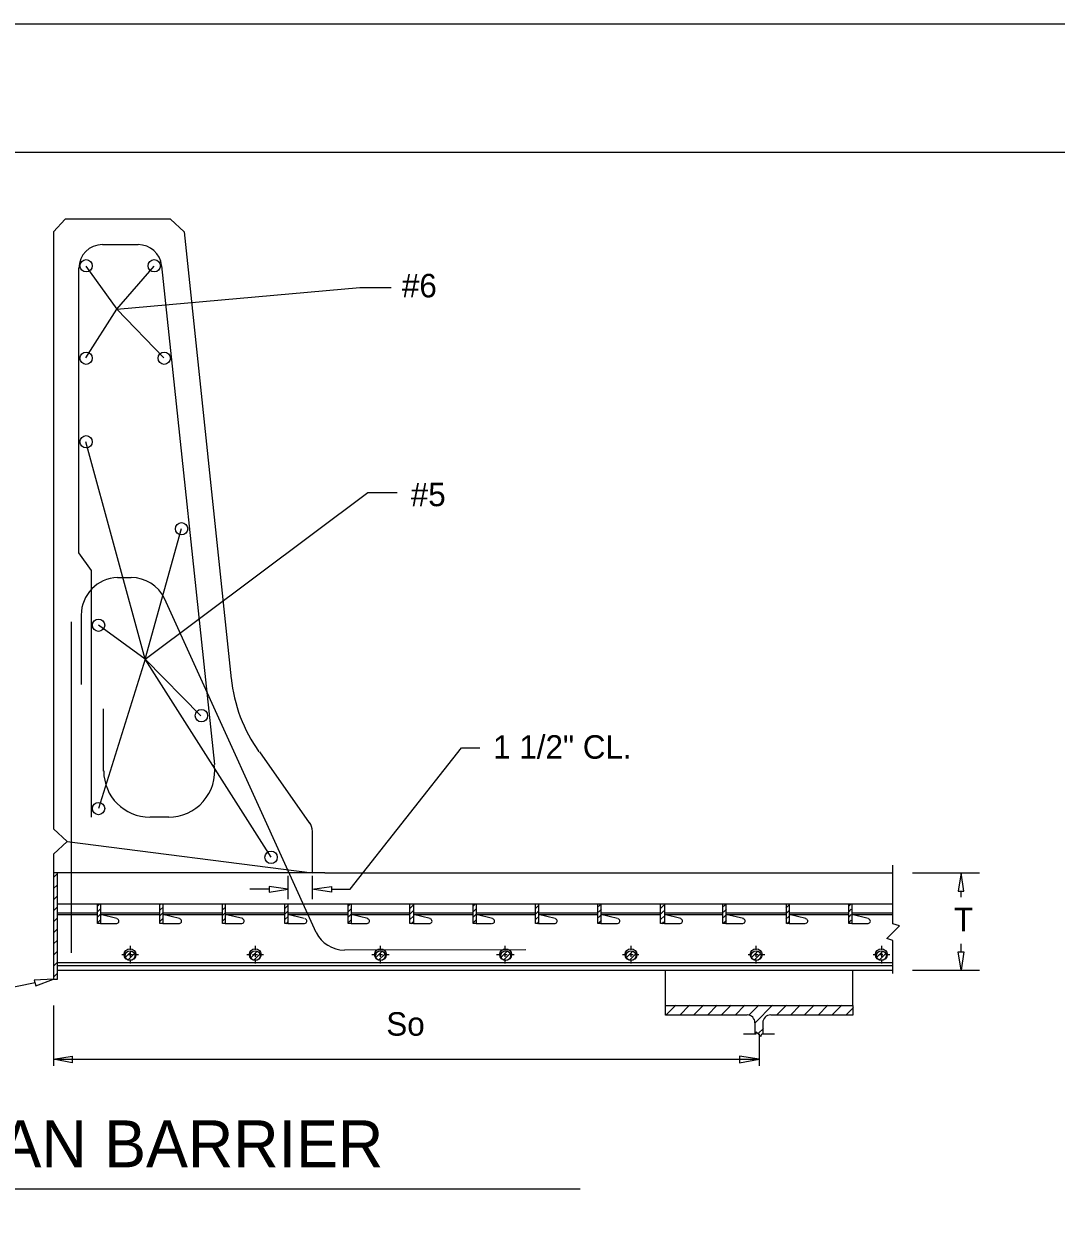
# Model space of a CAD drawing. Extents: x -24512 to -22484, y 4569 to 6351.
# Drawn here: x -23745.6 to -23613.7, y 6199 to 6351 of the extents above; entities that cross this region are included whole.
import ezdxf

# ---------------------------------------------------------------- set-up
doc = ezdxf.new("R2010")
doc.units = 0
for name, color, linetype in [('10', 7, 'Continuous'), ('11', 7, 'Continuous'), ('2', 7, 'Continuous'), ('4', 7, 'Continuous'), ('5', 7, 'Continuous'), ('8', 7, 'Continuous'), ('PLT-BNDY', 7, 'Continuous')]:
    doc.layers.add(name, color=color, linetype=linetype)

# ---------------------------------------------------------------- blocks, each defined once
blk = doc.blocks.new('JUQ000')
at = {"layer": '4'}
for p, q in [((71.0975, 21.771125), (71.421875, 22.095625)), ((71.237875, 21.6265), (71.566625, 21.95525))]:
    blk.add_line(p, q, dxfattribs=at)
blk = doc.blocks.new('JUQ001')
at = {"layer": '4'}
for p, q in [((66.419125, 24.506), (66.4355, 24.522375)), ((66.419125, 24.220875), (66.570375, 24.372125)), ((66.419125, 23.93575), (66.570375, 24.087)), ((66.419125, 23.650625), (66.570375, 23.801875)), ((66.567875, 23.514375), (66.570375, 23.51675))]:
    blk.add_line(p, q, dxfattribs=at)
blk = doc.blocks.new('_X')
at = {"layer": '4'}
for p, q in [((63.193375, 24.416625), (63.299125, 24.522375)), ((63.193375, 24.1315), (63.3445, 24.282625)), ((63.193375, 23.846375), (63.3445, 23.9975)), ((63.193375, 23.56125), (63.3445, 23.712375))]:
    blk.add_line(p, q, dxfattribs=at)
blk = doc.blocks.new('JUQ004')
at = {"layer": '4'}
for p, q in [((69.644875, 24.310375), (69.796125, 24.4615)), ((69.644875, 24.02525), (69.796125, 24.176375)), ((69.644875, 23.740125), (69.796125, 23.89125)), ((69.70425, 23.514375), (69.796125, 23.60625))]:
    blk.add_line(p, q, dxfattribs=at)
blk = doc.blocks.new('JUQ002')
at = {"layer": '4'}
for p, q in [((72.87075, 24.39975), (72.993375, 24.522375)), ((72.87075, 24.114625), (73.021875, 24.265875)), ((72.87075, 23.8295), (73.021875, 23.98075)), ((72.87075, 23.544375), (73.021875, 23.695625))]:
    blk.add_line(p, q, dxfattribs=at)
blk = doc.blocks.new('JUQ003')
at = {"layer": '4'}
for p, q in [((89.35625, 63.69525), (89.860375, 64.19925)), ((90.069125, 63.69525), (90.573125, 64.19925)), ((90.781875, 63.69525), (91.285875, 64.19925)), ((91.49475, 63.69525), (91.99875, 64.19925)), ((92.2075, 63.69525), (92.7115, 64.19925)), ((92.920375, 63.69525), (93.424375, 64.19925)), ((93.628875, 63.691), (94.137125, 64.19925)), ((93.972625, 63.321875), (94.85, 64.19925)), ((95.05875, 63.69525), (95.56275, 64.19925)), ((95.7715, 63.69525), (96.275625, 64.19925)), ((96.484375, 63.69525), (96.988375, 64.19925)), ((97.197125, 63.69525), (97.70125, 64.19925)), ((97.91, 63.69525), (98.414, 64.19925)), ((98.62275, 63.69525), (99.014, 64.0865)), ((94.121125, 62.757625), (94.377, 63.013375))]:
    blk.add_line(p, q, dxfattribs=at)

msp = doc.modelspace()

# ---------------------------------------------------------------- linework, layer by layer
at = {"layer": '10'}
for p, q in [((-23737.67, 6320.06), (-23733.68, 6314.58)), ((-23733.68, 6314.58), (-23728.94, 6320.06)), ((-23737.67, 6308.34), (-23733.68, 6314.58)), ((-23733.68, 6314.58), (-23727.69, 6308.34)), ((-23730.06, 6269.81), (-23737.67, 6297.62)), ((-23730.06, 6269.81), (-23701.63, 6291.14)), ((-23701.63, 6291.14), (-23697.89, 6291.14)), ((-23730.06, 6269.81), (-23725.45, 6286.52)), ((-23733.6, 6280.26), (-23731.87, 6280.26)), ((-23730.06, 6269.81), (-23736.05, 6274.18)), ((-23730.06, 6269.81), (-23736.05, 6250.74)), ((-23713.98, 6244.5), (-23730.06, 6269.81)), ((-23722.95, 6262.58), (-23730.06, 6269.81)), ((-23703.88, 6240.39), (-23689.66, 6258.46)), ((-23689.66, 6258.46), (-23687.29, 6258.46)), ((-23711.86, 6242.13), (-23711.86, 6239.14)), ((-23708.74, 6242.13), (-23708.74, 6239.14)), ((-23632.03, 6242.51), (-23623.44, 6242.51)), ((-23714.23, 6240.39), (-23716.72, 6240.39)), ((-23706.25, 6240.39), (-23703.88, 6240.39)), ((-23625.81, 6239.39), (-23625.81, 6240.14)), ((-23731.93, 6232.66), (-23731.93, 6233.16)), ((-23715.97, 6232.66), (-23715.97, 6233.16)), ((-23700.01, 6232.66), (-23700.01, 6233.16)), ((-23684.05, 6232.66), (-23684.05, 6233.16)), ((-23667.97, 6232.66), (-23667.97, 6233.16)), ((-23652.01, 6232.66), (-23652.01, 6233.16)), ((-23635.92, 6232.66), (-23635.92, 6233.16)), ((-23625.81, 6232.41), (-23625.81, 6233.41)), ((-23732.55, 6232.03), (-23733.05, 6232.03)), ((-23731.68, 6232.03), (-23732.3, 6232.03)), ((-23731.93, 6231.78), (-23731.93, 6232.28)), ((-23730.93, 6232.03), (-23731.43, 6232.03)), ((-23716.59, 6232.03), (-23717.09, 6232.03)), ((-23715.72, 6232.03), (-23716.34, 6232.03)), ((-23715.97, 6231.78), (-23715.97, 6232.28)), ((-23714.97, 6232.03), (-23715.47, 6232.03)), ((-23700.51, 6232.03), (-23701.13, 6232.03)), ((-23699.76, 6232.03), (-23700.26, 6232.03)), ((-23700.01, 6231.78), (-23700.01, 6232.28)), ((-23698.89, 6232.03), (-23699.39, 6232.03)), ((-23684.55, 6232.03), (-23685.17, 6232.03)), ((-23683.8, 6232.03), (-23684.3, 6232.03)), ((-23684.05, 6231.78), (-23684.05, 6232.28)), ((-23682.93, 6232.03), (-23683.43, 6232.03)), ((-23668.59, 6232.03), (-23669.09, 6232.03)), ((-23667.72, 6232.03), (-23668.22, 6232.03)), ((-23667.97, 6231.78), (-23667.97, 6232.28)), ((-23666.97, 6232.03), (-23667.34, 6232.03)), ((-23652.63, 6232.03), (-23653, 6232.03)), ((-23651.76, 6232.03), (-23652.26, 6232.03)), ((-23652.01, 6231.78), (-23652.01, 6232.28)), ((-23650.88, 6232.03), (-23651.38, 6232.03)), ((-23636.54, 6232.03), (-23637.04, 6232.03)), ((-23635.8, 6232.03), (-23636.3, 6232.03)), ((-23635.92, 6231.78), (-23635.92, 6232.28)), ((-23634.92, 6232.03), (-23635.42, 6232.03)), ((-23731.93, 6230.91), (-23731.93, 6231.41)), ((-23715.97, 6230.91), (-23715.97, 6231.41)), ((-23700.01, 6230.91), (-23700.01, 6231.41)), ((-23684.05, 6230.91), (-23684.05, 6231.41)), ((-23667.97, 6230.91), (-23667.97, 6231.41)), ((-23652.01, 6230.91), (-23652.01, 6231.41)), ((-23635.92, 6230.91), (-23635.92, 6231.41)), ((-23632.03, 6230.04), (-23623.44, 6230.04)), ((-23744.15, 6228.42), (-23757.24, 6225.8)), ((-23741.78, 6225.55), (-23741.78, 6217.82)), ((-23651.63, 6221.93), (-23651.63, 6217.82)), ((-23741.78, 6218.69), (-23651.63, 6218.69))]:
    msp.add_line(p, q, dxfattribs=at)
msp.add_lwpolyline([(-23733.68, 6314.58), (-23702.63, 6317.32), (-23698.64, 6317.32)], dxfattribs=at)
for points in [[(-23626.19, 6240.14), (-23625.44, 6240.14), (-23625.81, 6242.51)], [(-23714.23, 6240.76), (-23714.23, 6240.01), (-23711.86, 6240.39)], [(-23706.25, 6240.76), (-23706.25, 6240.01), (-23708.74, 6240.39)], [(-23626.19, 6232.41), (-23625.44, 6232.41), (-23625.81, 6230.04)], [(-23744.27, 6228.79), (-23744.03, 6228.04), (-23741.78, 6228.92)], [(-23739.41, 6219.07), (-23739.41, 6218.19), (-23741.78, 6218.69)], [(-23654.13, 6219.07), (-23654.13, 6218.19), (-23651.63, 6218.69)]]:
    msp.add_lwpolyline(points, close=True, dxfattribs=at)
for centre, radius, start, end in [((-23735.54, 6319.81), 3, 90, 180), ((-23730.96, 6319.81), 3, 6.0542, 90), ((-23733.45, 6275.46), 4.8, 91.8539, 180), ((-23731.91, 6275.46), 4.8, 26.0753, 89.5289), ((-23704.62, 6236.63), 4, 206.1039, 270.062)]:
    msp.add_arc(centre, radius, start, end, dxfattribs=at)
at = {"layer": '11'}
msp.add_line((-23674.47, 6202.06), (-23795.04, 6202.06), dxfattribs=at)
at = {"layer": '2'}
msp.add_line((-24137.79, 6334.63), (-23353.75, 6334.63), dxfattribs=at)
at = {"layer": '4'}
for p, q in [((-23741.78, 6241.89), (-23741.32, 6242.35)), ((-23741.78, 6240.48), (-23741.32, 6240.94)), ((-23741.78, 6239.06), (-23741.32, 6239.52)), ((-23741.78, 6237.65), (-23741.32, 6238.11)), ((-23741.78, 6236.24), (-23741.32, 6236.69)), ((-23741.78, 6234.82), (-23741.32, 6235.28)), ((-23741.78, 6233.41), (-23741.32, 6233.86)), ((-23741.78, 6231.99), (-23741.32, 6232.45)), ((-23741.78, 6230.58), (-23741.32, 6231.04)), ((-23741.78, 6229.16), (-23741.32, 6229.62))]:
    msp.add_line(p, q, dxfattribs=at)
at = {"layer": '5'}
for p, q in [((-23707.12, 6242.51), (-23634.54, 6242.51)), ((-23741.28, 6238.52), (-23736.17, 6238.52)), ((-23735.8, 6238.52), (-23728.19, 6238.52)), ((-23727.82, 6238.52), (-23720.21, 6238.52)), ((-23719.84, 6238.52), (-23712.23, 6238.52)), ((-23711.86, 6238.52), (-23704.13, 6238.52)), ((-23703.75, 6238.52), (-23696.27, 6238.52)), ((-23695.77, 6238.52), (-23688.17, 6238.52)), ((-23687.79, 6238.52), (-23680.19, 6238.52)), ((-23679.81, 6238.52), (-23672.21, 6238.52)), ((-23671.83, 6238.52), (-23664.23, 6238.52)), ((-23663.73, 6238.52), (-23656.25, 6238.52)), ((-23655.87, 6238.52), (-23648.14, 6238.52)), ((-23647.77, 6238.52), (-23640.16, 6238.52)), ((-23639.79, 6238.52), (-23634.54, 6238.52)), ((-23741.28, 6237.4), (-23736.17, 6237.4)), ((-23741.28, 6237.15), (-23736.17, 6237.15)), ((-23735.8, 6237.4), (-23728.19, 6237.4)), ((-23735.8, 6237.15), (-23728.19, 6237.15)), ((-23733.68, 6236.65), (-23735.8, 6237.15)), ((-23735.8, 6236.02), (-23733.68, 6236.02)), ((-23727.82, 6237.4), (-23720.21, 6237.4)), ((-23727.82, 6237.15), (-23720.21, 6237.15)), ((-23725.7, 6236.65), (-23727.82, 6237.15)), ((-23727.82, 6236.02), (-23725.7, 6236.02)), ((-23719.84, 6237.4), (-23712.23, 6237.4)), ((-23719.84, 6237.15), (-23712.23, 6237.15)), ((-23717.59, 6236.65), (-23719.84, 6237.15)), ((-23719.84, 6236.02), (-23717.72, 6236.02)), ((-23711.86, 6237.4), (-23704.13, 6237.4)), ((-23711.86, 6237.15), (-23704.13, 6237.15)), ((-23709.74, 6236.65), (-23711.86, 6237.15)), ((-23711.86, 6236.02), (-23709.74, 6236.02)), ((-23703.75, 6237.4), (-23696.27, 6237.4)), ((-23703.75, 6237.15), (-23696.27, 6237.15)), ((-23701.63, 6236.65), (-23703.75, 6237.15)), ((-23703.75, 6236.02), (-23701.76, 6236.02)), ((-23695.77, 6237.4), (-23688.17, 6237.4)), ((-23695.77, 6237.15), (-23688.17, 6237.15)), ((-23693.65, 6236.65), (-23695.77, 6237.15)), ((-23695.77, 6236.02), (-23693.65, 6236.02)), ((-23687.79, 6237.4), (-23680.19, 6237.4)), ((-23687.79, 6237.15), (-23680.19, 6237.15)), ((-23685.67, 6236.65), (-23687.79, 6237.15)), ((-23687.79, 6236.02), (-23685.8, 6236.02)), ((-23679.81, 6237.4), (-23672.21, 6237.4)), ((-23679.81, 6237.15), (-23672.21, 6237.15)), ((-23677.69, 6236.65), (-23679.81, 6237.15)), ((-23679.81, 6236.02), (-23677.69, 6236.02)), ((-23671.83, 6237.4), (-23664.23, 6237.4)), ((-23671.83, 6237.15), (-23664.23, 6237.15)), ((-23669.71, 6236.65), (-23671.83, 6237.15)), ((-23671.83, 6236.02), (-23669.71, 6236.02)), ((-23663.73, 6237.4), (-23656.25, 6237.4)), ((-23663.73, 6237.15), (-23656.25, 6237.15)), ((-23661.61, 6236.65), (-23663.73, 6237.15)), ((-23663.73, 6236.02), (-23661.73, 6236.02)), ((-23655.87, 6237.4), (-23648.14, 6237.4)), ((-23655.87, 6237.15), (-23648.14, 6237.15)), ((-23653.63, 6236.65), (-23655.87, 6237.15)), ((-23655.87, 6236.02), (-23653.75, 6236.02)), ((-23647.77, 6237.4), (-23640.16, 6237.4)), ((-23647.77, 6237.15), (-23640.16, 6237.15)), ((-23645.65, 6236.65), (-23647.77, 6237.15)), ((-23647.77, 6236.02), (-23645.77, 6236.02)), ((-23639.79, 6237.4), (-23634.54, 6237.4)), ((-23637.67, 6236.65), (-23639.79, 6237.15)), ((-23639.79, 6237.15), (-23634.54, 6237.15)), ((-23639.79, 6236.02), (-23637.67, 6236.02)), ((-23741.28, 6231.04), (-23634.54, 6231.04)), ((-23741.28, 6230.66), (-23634.54, 6230.66)), ((-23741.28, 6230.04), (-23634.54, 6230.04)), ((-23663.6, 6225.55), (-23663.6, 6230.04)), ((-23639.66, 6225.55), (-23639.66, 6230.04)), ((-23663.6, 6224.3), (-23663.6, 6225.55)), ((-23663.6, 6225.55), (-23639.66, 6225.55)), ((-23639.66, 6225.55), (-23639.66, 6224.3)), ((-23653.13, 6224.3), (-23663.6, 6224.3)), ((-23639.66, 6224.3), (-23650.14, 6224.3)), ((-23652.13, 6221.93), (-23652.13, 6223.31)), ((-23651.13, 6223.31), (-23651.13, 6221.93)), ((-23653.63, 6221.93), (-23652.13, 6221.93)), ((-23651.13, 6221.93), (-23649.64, 6221.93))]:
    msp.add_line(p, q, dxfattribs=at)
for points in [[(-23741.78, 6228.92), (-23741.28, 6228.92), (-23741.28, 6242.51), (-23741.78, 6242.51)], [(-23735.8, 6238.52), (-23735.8, 6236.02), (-23736.17, 6236.02), (-23736.17, 6238.52)], [(-23727.82, 6238.52), (-23727.82, 6236.02), (-23728.19, 6236.02), (-23728.19, 6238.52)], [(-23719.84, 6238.52), (-23719.84, 6236.02), (-23720.21, 6236.02), (-23720.21, 6238.52)], [(-23711.86, 6238.52), (-23711.86, 6236.02), (-23712.23, 6236.02), (-23712.23, 6238.52)], [(-23703.75, 6238.52), (-23703.75, 6236.02), (-23704.13, 6236.02), (-23704.13, 6238.52)], [(-23695.77, 6238.52), (-23695.77, 6236.02), (-23696.27, 6236.02), (-23696.27, 6238.52)], [(-23687.79, 6238.52), (-23687.79, 6236.02), (-23688.17, 6236.02), (-23688.17, 6238.52)], [(-23679.81, 6238.52), (-23679.81, 6236.02), (-23680.19, 6236.02), (-23680.19, 6238.52)], [(-23671.83, 6238.52), (-23671.83, 6236.02), (-23672.21, 6236.02), (-23672.21, 6238.52)], [(-23663.73, 6238.52), (-23663.73, 6236.02), (-23664.23, 6236.02), (-23664.23, 6238.52)], [(-23655.87, 6238.52), (-23655.87, 6236.02), (-23656.25, 6236.02), (-23656.25, 6238.52)], [(-23647.77, 6238.52), (-23647.77, 6236.02), (-23648.14, 6236.02), (-23648.14, 6238.52)], [(-23639.79, 6238.52), (-23639.79, 6236.02), (-23640.16, 6236.02), (-23640.16, 6238.52)]]:
    msp.add_lwpolyline(points, close=True, dxfattribs=at)
for points in [[(-23634.54, 6229.62), (-23634.54, 6233.86), (-23635.29, 6234.11), (-23633.66, 6235.73), (-23634.54, 6235.98), (-23634.54, 6243.46)], [(-23652.13, 6221.93), (-23652.01, 6221.93), (-23652.01, 6222.18), (-23651.38, 6221.56), (-23651.26, 6221.93), (-23651.13, 6221.93)]]:
    msp.add_lwpolyline(points, dxfattribs=at)
for centre, radius in [((-23732.01, 6232.05), 0.75), ((-23732.01, 6231.92), 0.625), ((-23716.01, 6232.05), 0.75), ((-23716.01, 6231.92), 0.625), ((-23700.01, 6232.05), 0.75), ((-23700.01, 6231.92), 0.625), ((-23684.01, 6232.05), 0.75), ((-23684.01, 6231.92), 0.625), ((-23668, 6232.05), 0.75), ((-23668, 6231.92), 0.625), ((-23652, 6232.05), 0.75), ((-23652, 6231.92), 0.625), ((-23636, 6232.05), 0.75), ((-23636, 6231.92), 0.625)]:
    msp.add_circle(centre, radius, dxfattribs=at)
for centre, radius, start, end in [((-23733.73, 6236.33), 0.305, 271.249, 76.5605), ((-23725.72, 6236.33), 0.305, 271.249, 76.5605), ((-23717.72, 6236.33), 0.305, 271.249, 76.5605), ((-23709.72, 6236.33), 0.305, 271.249, 76.5605), ((-23701.72, 6236.33), 0.305, 271.249, 76.5605), ((-23693.72, 6236.33), 0.305, 271.249, 76.5605), ((-23685.72, 6236.33), 0.305, 271.249, 76.5605), ((-23677.72, 6236.33), 0.305, 271.249, 76.5605), ((-23669.72, 6236.33), 0.305, 271.249, 76.5605), ((-23661.71, 6236.33), 0.305, 271.249, 76.5605), ((-23653.71, 6236.33), 0.305, 271.249, 76.5605), ((-23645.71, 6236.33), 0.305, 271.249, 76.5605), ((-23637.71, 6236.33), 0.305, 271.249, 76.5605), ((-23653.15, 6223.33), 1, 0, 90), ((-23650.15, 6223.33), 1, 90, 180)]:
    msp.add_arc(centre, radius, start, end, dxfattribs=at)
at = {"layer": '8'}
for p, q in [((-23735.54, 6322.81), (-23730.96, 6322.81)), ((-23738.54, 6283.41), (-23738.54, 6319.81)), ((-23727.97, 6320.12), (-23721.21, 6256.35)), ((-23736.92, 6249.61), (-23736.92, 6280.29)), ((-23708.21, 6234.87), (-23727.6, 6277.57)), ((-23739.49, 6232.27), (-23739.49, 6274.58)), ((-23738.25, 6275.46), (-23738.25, 6266.57)), ((-23735.42, 6255.48), (-23735.42, 6263.46)), ((-23727.07, 6249.61), (-23729.44, 6249.61)), ((-23681.43, 6232.66), (-23704.62, 6232.63))]:
    msp.add_line(p, q, dxfattribs=at)
msp.add_lwpolyline([(-23736.92, 6280.29), (-23736.92, 6281.16), (-23738.54, 6283.41)], dxfattribs=at)
for centre in [(-23737.62, 6320.1), (-23728.91, 6320.1), (-23737.62, 6308.29), (-23727.64, 6308.29), (-23737.62, 6297.6), (-23725.42, 6286.48), (-23736.03, 6274.15), (-23722.89, 6262.59), (-23736.03, 6250.71), (-23713.99, 6244.48)]:
    msp.add_circle(centre, 0.788, dxfattribs=at)
for centre, start, end in [((-23727.1, 6255.52), 270, 7.4397), ((-23729.46, 6255.52), 180, 270)]:
    msp.add_arc(centre, 5.91, start, end, dxfattribs=at)
at = {"layer": 'PLT-BNDY'}
for p, q in [((-23741.78, 6324.43), (-23740.28, 6326.05)), ((-23726.82, 6326.05), (-23740.28, 6326.05)), ((-23725.07, 6324.43), (-23726.82, 6326.05)), ((-23741.78, 6324.43), (-23741.78, 6248.12)), ((-23725.07, 6324.43), (-23719.09, 6267.32)), ((-23715.47, 6257.97), (-23709.11, 6248.87)), ((-23741.78, 6248.12), (-23740.04, 6246.5)), ((-23708.74, 6247.87), (-23708.74, 6242.51)), ((-23741.78, 6244.88), (-23740.04, 6246.5)), ((-23740.04, 6246.5), (-23708.74, 6242.51)), ((-23741.78, 6244.88), (-23741.78, 6242.51)), ((-23707.12, 6242.51), (-23741.78, 6242.51))]:
    msp.add_line(p, q, dxfattribs=at)
msp.add_lwpolyline([(-23338.75, 5757.04), (-24179.75, 5757.04), (-24179.75, 6351.04), (-23338.75, 6351.04)], close=True, dxfattribs=at)
for centre, radius, start, end in [((-23699.51, 6269.43), 19.69, 185.9906, 215.5377), ((-23710.68, 6247.8), 1.97, 0, 35.5377)]:
    msp.add_arc(centre, radius, start, end, dxfattribs=at)

# ---------------------------------------------------------------- block references
at = {"layer": '4', "xscale": 2.4803976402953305, "yscale": 2.4803976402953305}
for name, p in [('_X', (-23892.9, 6177.67)), ('JUQ001', (-23892.9, 6177.67)), ('JUQ001', (-23884.92, 6177.67)), ('JUQ004', (-23884.92, 6177.67)), ('JUQ002', (-23884.92, 6177.67)), ('JUQ004', (-23868.96, 6177.67)), ('JUQ002', (-23868.96, 6177.67)), ('JUQ004', (-23852.88, 6177.67)), ('JUQ002', (-23852.88, 6177.67)), ('JUQ004', (-23836.92, 6177.67)), ('JUQ002', (-23836.92, 6177.67)), ('JUQ004', (-23820.96, 6177.67)), ('JUQ002', (-23820.96, 6177.67)), ('JUQ000', (-23908.99, 6177.67)), ('JUQ000', (-23892.9, 6177.67)), ('JUQ000', (-23876.94, 6177.67)), ('JUQ000', (-23860.98, 6177.67)), ('JUQ000', (-23844.9, 6177.67)), ('JUQ000', (-23828.94, 6177.67)), ('JUQ000', (-23812.98, 6177.67)), ('JUQ003', (-23885.17, 6066.32))]:
    msp.add_blockref(name, p, dxfattribs=at)

# ---------------------------------------------------------------- texts
at = {"layer": '10'}
for s, p in [('#6', (-23697.27, 6316.07)), ('#5', (-23696.13, 6289.37)), ('1 1/2" CL.', (-23685.61, 6257.09)), ('T', (-23626.74, 6235.04)), ('So', (-23699.26, 6221.68))]:
    msp.add_text(s, height=3, dxfattribs=at).set_placement(p)
at = {"layer": '11'}
msp.add_text('SPLIT MEDIAN BARRIER', height=6.0008, dxfattribs=at).set_placement((-23793.28, 6204.85))

doc.saveas('drawing.dxf')
